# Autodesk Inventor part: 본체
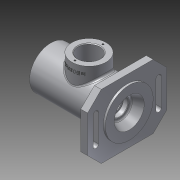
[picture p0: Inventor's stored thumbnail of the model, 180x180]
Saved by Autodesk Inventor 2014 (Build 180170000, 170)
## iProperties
Created: 2017-10
Part Number: 본체
Material: 알루미늄 6061
Document SubType Name: Modeling
Designer: geosung1
Density: 2.71 g/cm^3
Appearance: 알루미늄 - 평지
Mass: 740.872 g
Surface Area: 653.378 cm^2
Volume: 273.385 cm^3
Author: geosung1
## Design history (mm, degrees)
sketch "스케치1"
  geometry: L1 (-57.5, 0)-(57.5, 0); L2 (-57.5, 0)-(-57.5, 31); L3 (-57.5, 31)-(54.5, 31); L4 (54.5, 31)-(54.5, 35); L5 (54.5, 35)-(57.5, 35); L6 (57.5, 35)-(57.5, 22); L7 (57.5, 22)-(43.5, 16); L8 (43.5, 16)-(43.5, 12.8); L9 (42.8, 12.5)-(36.2, 12.5); L10 (36.2, 12.5)-(36.2, 10); L11 (36.2, 10)-(33.5, 10); L12 (33.5, 10)-(33.5, 16.5); L13 (33.5, 16.5)-(28.5, 16.5); L14 (28.5, 16.5)-(28.5, 17.5); L15 (28.5, 17.5)-(17.5, 17.5); L16 (17.5, 17.5)-(17.5, 26); L17 (17.5, 26)-(-20.5, 26); L18 (-20.5, 26)-(-20.5, 17.5); L19 (-20.5, 17.5)-(-31.5, 17.5); L20 (-31.5, 17.5)-(-31.5, 18.5); L21 (-31.5, 18.5)-(-33.25, 18.5); L22 (-33.25, 18.5)-(-33.25, 17.5); L23 (-33.25, 17.5)-(-36.5, 17.5); L24 (-36.5, 17.5)-(-36.5, 20); L25 (-36.5, 20)-(-45.5, 20); L26 (-45.5, 20)-(-45.5, 24); L27 (-45.5, 24)-(-48.5, 24); L28 (-48.5, 24)-(-48.5, 0); L29 (42.8, 12.5)-(43.5, 12.904); 2 further points
  constraints: 58 end point, 23 parallel, 3 perpendicular, 2 point on line, 1 coincident, 1 horizontal, 1 midpoint, 1 vertical alignment
  dimensions: "d0" = 115 distance of L1.start L1.end; "d1" = 62 diameter of L2.end L1; "d2" = 70 diameter of L5.end L1; "d3" = 3 distance of L4.end L5.end; "d4" = 44 diameter of L6.end L1; "d5" = 32 diameter of L7.end L1; "d6" = 25 diameter of L9.end L1; "d7" = 20 diameter of L11.end L1; "d8" = 33 diameter of L13.end L1; "d9" = 35 diameter of L15.end L1; "d10" = 52 diameter of L17 L1; "d11" = 35 diameter of L18.end L1; "d12" = 37 diameter of L20.end L1; "d13" = 35 diameter of L23 L1; "d14" = 40 diameter of L25 L1; "d15" = 48 diameter of L27.end L1; "d17" = 9 distance of L28.end L1.start; "d18" = 3 distance of L26.end L27.end; "d19" = 21 horizontal distance of L23.end L1.start; "d20" = 1.75 distance of L20.end L21.end; "d21" = 26 horizontal distance of L1.start L19.end; "d22" = 11 distance of L18.end L19.end; "d23" = 60 horizontal distance of L13.end L19.end; "d24" = 38 distance of L16.end L17.end; "d25" = 5 distance of L12.end L13.end; "d27" = 0.7 horizontal distance of L9.start L8.end; "d28" = 7.3 horizontal distance of L8.end L10.end; "d29" = 14 horizontal distance of L6.end L7.end; "d30" = 30 deg angle of L29 L9; "d31" = 3.2 distance of L7.end L8.end
revolve "회전1" sketch "스케치1" stored, may be unused: angle "d32" = 90 deg
node "작업 평면1"
sketch "스케치2"
  geometry: L1 (-58, 47)-(58, 47); L2 (58, 47)-(58, -47); L3 (58, -47)-(-58, -47); L4 (-58, -47)-(-58, 47); C1 r 31 at (0, 0) reference; 3 further points
  constraints: 8 end point, 2 midpoint, 2 parallel, 1 horizontal, 1 horizontal alignment, 1 perpendicular, 1 vertical alignment
  dimensions: "d34" = 116 distance of L1.start L1.end; "d35" = 94 distance of L1.end L2.end
extrude "돌출1" join sketch "스케치2" distance "d36" = 10; taper "d37" = 0 deg
chamfer "모따기1" distance "d38" = 20; stored, may be unused: second distance "d39" = 2, angle "d40" = 45 deg
sketch "스케치3"
  geometry: L1 (-50, -20)-(-50, 20); L2 (-42, 20)-(-42, -20); C1 r 35 at (0, 0) reference; A1 r 4 centre (-46, 20) between (-42, 20) and (-50, 20); A2 r 4 centre (-46, -20) between (-50, -20) and (-42, -20)
  constraints: 4 end point, 4 point on circle, 4 tangent, 2 centre point, 1 equal radius, 1 vertical alignment
  dimensions: "d41" = 46 horizontal distance of C1.centre A2.centre; "d42" = 8 diameter of A1; "d43" = 40 distance of A1.centre A2.centre; "d44" = 20 vertical distance of C1.centre A2.centre
extrude "돌출2" cut sketch "스케치3" distance "d45" = 10; taper "d46" = 0 deg
hole "구멍1" diameter "d49" = 40.376; stored, may be unused: countersink angle "d53" = 90 deg, drill point angle "d55" = 0 deg; dims "d47" = 10, "d48" = 10, "d50" = 9, "d51" = 4, "d52" = 2, "d54" = 9
node "작업 평면2"
sketch "스케치4"
  geometry: L1 (57.5, 31)-(57.5, -31) reference; C1 r 25 at (1.5, 0); 1 further point
  constraints: 1 centre point, 1 horizontal alignment
  dimensions: "d57" = 50 diameter of C1; "d58" = 56 distance from line of C1.centre L1
extrude "돌출3" join sketch "스케치4" stored distance "d59" = 10; taper "d60" = 0 deg
hole "구멍2" diameter "d63" = 32; stored, may be unused: countersink angle "d67" = 90 deg, drill point angle "d69" = 0 deg; dims "d61" = 10, "d62" = 10, "d64" = 9, "d65" = 4, "d66" = 2, "d68" = 35.9875
sketch "스케치5" dims "d70" = 41
  geometry: L1 (0, 0)-(0, 20.5); C1 r 25 at (0, 0) reference; 1 further point
  constraints: 2 end point, 1 coincident, 1 vertical, 1 vertical alignment, 2 other
hole "구멍3" sketch "스케치5" at (0, 20.5) diameter "d71" = 2.459; stored, may be unused: countersink angle "d75" = 90 deg, drill point angle "d77" = 118 deg; dims "d72" = 6, "d73" = 4, "d74" = 2, "d76" = 8
node "작업 평면3"
sketch "스케치6"
  geometry: L1 (-56, -78)-(-56, -16) reference; L2 (-25, 0)-(25, 0) reference; 2 further points
  constraints: 1 other
  dimensions: "d81" = 56 distance from line of point (0, -10) L1; "d82" = 10 distance from line of L2 point (0, -10)
feature "엠보싱1" sketch "스케치6" dims "d1" = 62, "d83" = 0.5, "d84" = 0
fillet "모깎기1" dims "d85" = 3
chamfer "모따기2" distance "d86" = 1; stored, may be unused: second distance "d87" = 2, angle "d88" = 45 deg
fillet "모깎기2" dims "d89" = 0.3, "d90" = 3
chamfer "모따기3" distance "d91" = 1; stored, may be unused: second distance "d92" = 2, angle "d93" = 45 deg
fillet "모깎기3" dims "d94" = 3
node "솔리드1"
mirror "대칭1"
pattern_circular "원형 패턴1" dims angle "d79" = 360 deg
other parameters: "d33" = -13, "d56" = 47
